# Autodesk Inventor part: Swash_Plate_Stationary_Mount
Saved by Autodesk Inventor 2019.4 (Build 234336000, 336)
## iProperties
Created: 2020-04
Part Number: Swash_Plate_Stationary_Mount
Material: Generic
Document SubType Name: Modeling
Designer: Administrator
Density: 1 g/cm^3
Appearance: Default
Title: Swash_Plate_Stationary_Mount v3
Author: Administrator
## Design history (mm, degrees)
feature "Body1"
feature "Body2"
body "Solid1"
body "Solid2"
